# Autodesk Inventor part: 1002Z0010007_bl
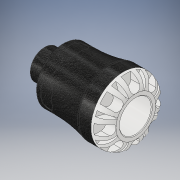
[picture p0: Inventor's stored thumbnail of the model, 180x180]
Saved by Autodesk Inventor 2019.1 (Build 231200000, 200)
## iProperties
Created: 2016-12
Part Number: 1002Z0010007_bl
Material: PVC-Piping
Description: PLASSON MALE ADAPTOR 1''CTS x 3/4''NPT SERIES 1
Document SubType Name: Modeling
Designer: KIM
Mass: 61.7504 g
Surface Area: 140.097 cm^2
Volume: 44.1074 cm^3
Density: 1.4 g/cm^3
Appearance: Black Cast
Author: KIM
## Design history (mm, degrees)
derived "1002Z.ipt"
feature "Solid1::1002Z.ipt" dims "ScaleForDerivedMember" = 10
tag "TaggingFeature1"
body "Solid1"
other parameters: "d0" = 82.042 [user parameter], "d1" = 22.72284 [user parameter], "d2" = 28.45 [user parameter], "d3" = 35.5625 [user parameter], "d4" = 57.912 [user parameter], "d6" = 54.102 [user parameter], "d8" = 49.2252 [user parameter], "d13" = 8.9398 [user parameter], "d14" = 8.9398 [user parameter], "d15" = 0 [user parameter], "d17" = 360 deg [user parameter], "d19" = 8 deg [user parameter], "d20" = 0.569 [user parameter], "d21" = 0.569 [user parameter], "d22" = 8 deg [user parameter], "d24" = 0 [user parameter], "d26" = 360 deg [user parameter], "d32" = 0.925 [user parameter], "d33" = 5.7912 [user parameter], "d34" = 26.441 [user parameter], "d35" = 3.55625 [user parameter], "d38" = 17.018 [user parameter], "d39" = 0.79323 [user parameter], "d42" = 9.9575 [user parameter], "d43" = 6.5435 [user parameter], "d45" = 17.52201 [user parameter], "d46" = 0 [user parameter], "d59" = 360 deg [user parameter], "d61" = 8.46387 [user parameter], "d62" = 0.569 [user parameter], "d64" = 0 [user parameter], "d65" = 0.57912 [user parameter], "d_" = 28.45 [user parameter], "E_" = 57.912 [user parameter], "H_" = 82.042 [user parameter], "l_" = 54.102 [user parameter], "R_" = 26.441 [user parameter], "l_2" = 17.018 [user parameter], "d9" = 11.17475 [user parameter], "d11" = 57.912 [user parameter], "d12" = 35.5625 [user parameter]
